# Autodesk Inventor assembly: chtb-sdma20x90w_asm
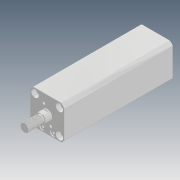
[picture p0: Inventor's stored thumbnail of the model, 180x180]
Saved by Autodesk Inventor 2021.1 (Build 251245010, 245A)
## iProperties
Company: Microsoft
Created: 2018-05
Part Number: chtb-sdma20x90w_asm
Description: STEP AP214
Document SubType Name: Assembly
Designer: user
Title: chtb-sdma20x90w_asm.STEP
Author: Windows
Revision Number: ÈÎºÎ
Sending System: SolidWorks 2015
Preprocessor: SwSTEP 2.0
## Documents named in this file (4)
- D:\Vault_2016\Projekty\Clamptek\Hydraulic\CHTB\CHTB-20\Inventor\CHTB-SDMA20x90W\chtb-sdma20x90w_asm.iam
- D:\Vault_2016\Projekty\Clamptek\Hydraulic\CHTB\CHTB-20\Inventor\CHTB-SDMA20x90W\CHTB-SDMA20X90NBT.ipt
- D:\Vault_2016\Projekty\Clamptek\Hydraulic\CHTB\CHTB-20\Inventor\CHTB-SDMA20x90W\CHTB-SDMA20X90WHSG.ipt
- D:\Vault_2016\Projekty\Clamptek\Hydraulic\CHTB\CHTB-20\Inventor\CHTB-SDMA20x90W\QG_3.ipt
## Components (3 placed, 3 different names)
1. CHTB-SDMA20X90NBT_1
2. CHTB-SDMA20X90WHSG_2
3. QG_3_3
